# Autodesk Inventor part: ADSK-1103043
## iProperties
Shininess: 50.0
Length Units: 11272
Angle Units: 11279
Time Units: 11290
Mass Units: 11286
Length Display Precision: 4
Angle Display Precision: 2
Compacted: True
Created: 2000-11
Part Number: ADSK-1103043
Document SubType Name: Modeling
Description: CRANKSHAFT
Mass: 18.2836 g
Surface Area: 21.3592 cm^2
Volume: 2.33209 cm^3
Density: 7.84 g/cm^3
Material: Steel, High Strength Low Alloy
Density: 0.0
Volumn: 0.0
Area: 0.0
PropertySet Name: Model Information
Control State: 0
Master: False
Checked Out: False
Author: Autodesk, Inc.
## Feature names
1. Extrusion7
2. Extrusion8
3. Chamfer2
4. Extrusion9
5. Fillet4
